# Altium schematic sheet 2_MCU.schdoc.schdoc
size 309 x 223 mm; Symbol: Artery_A4; Device: Artery_A4; Company: Artery Technology; Version: 1.1; Page Size: A4; @Project Name: AT-START-F423 V1.1; @Page Count: 4; @Update Date: 2024-04-30; @Create Date: 2023-04-24; @Schematic Name: AT-START-F423 V1.1; @Page No: 2; @Page Name: MCU
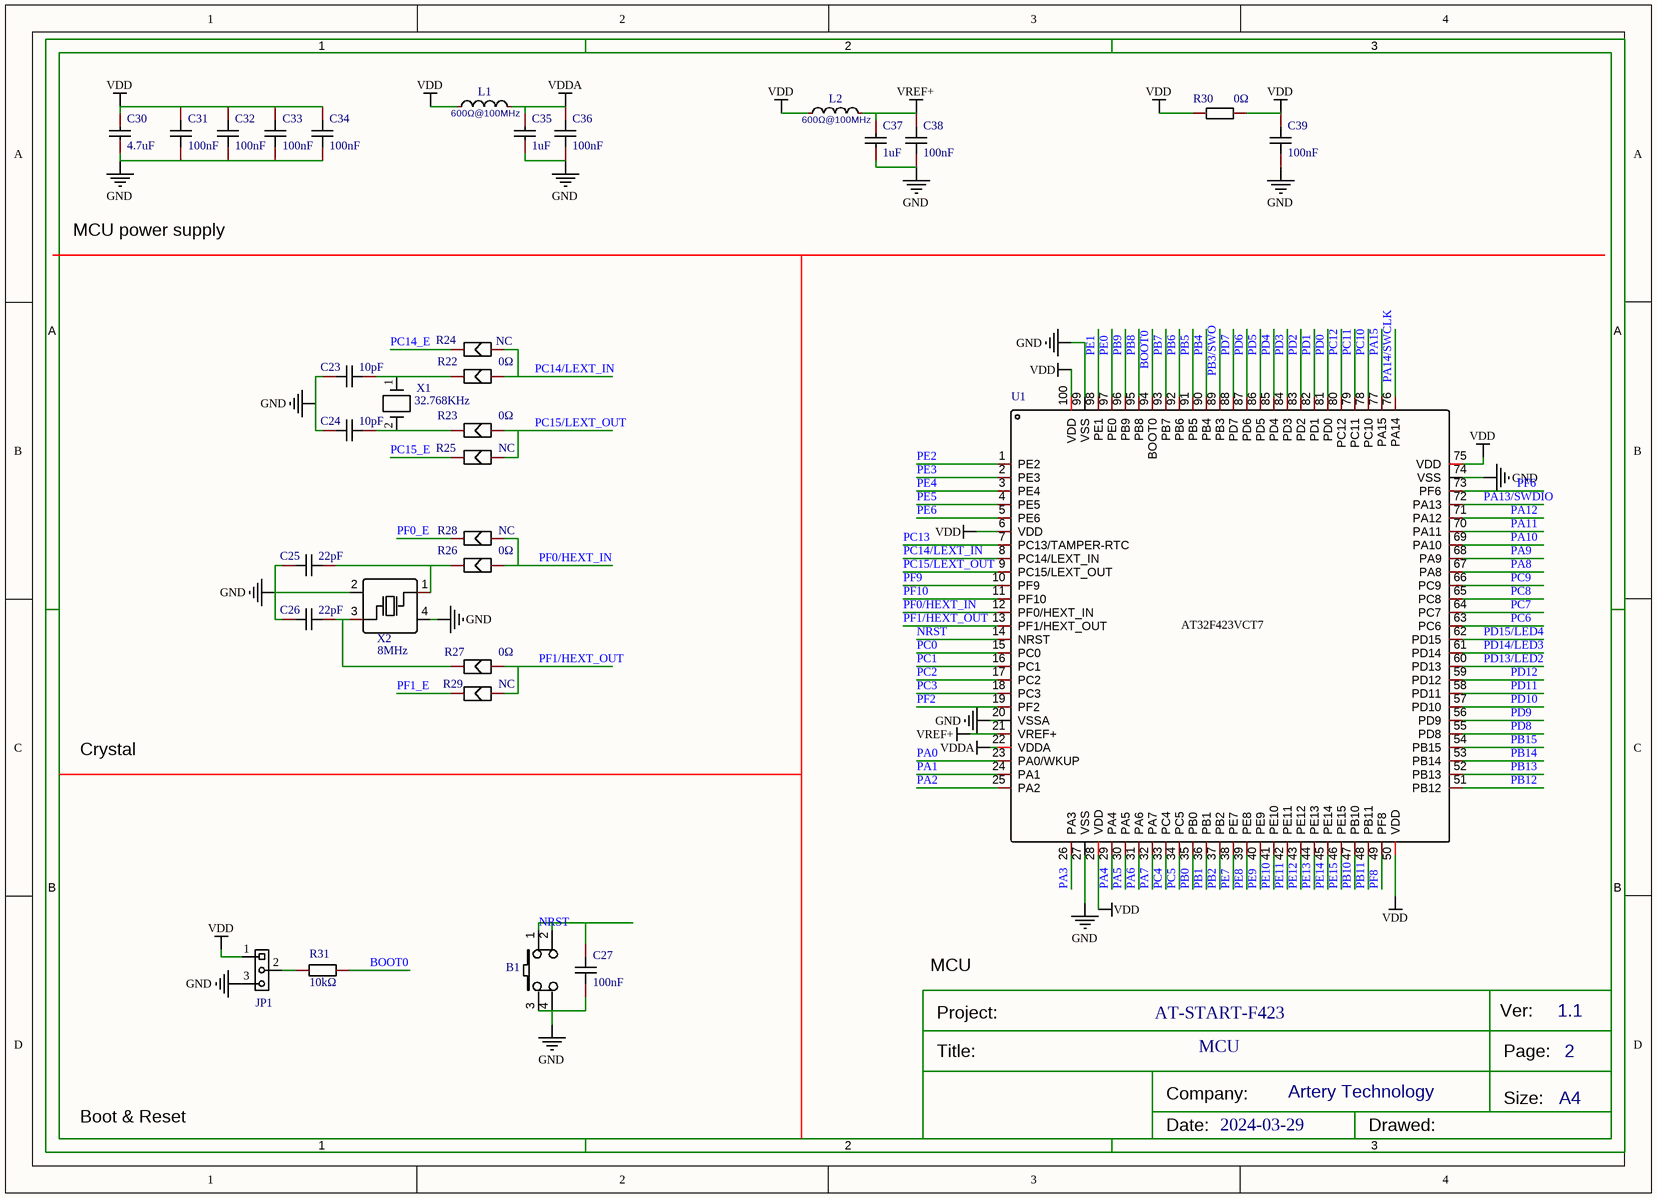
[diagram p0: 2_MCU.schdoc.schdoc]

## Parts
B1  BUTTON_SMT,6.0x6.0x4.5mm  [BUTTON_SMT_6*6*5]  (value not drawn)
C23  10pF  [0603_C-M]
C24  10pF  [0603_C-M]
C25  22pF  [0603_C-M(1)]
C26  22pF  [0603_C-M(1)]
C27  value 100nF  [C0603]  (hidden comment: CC0603KRX7R9BB104)
C30  value 4.7uF  [C0603]  (hidden comment: CL10A475KO8NNNC)
C31  value 100nF  [C0603]  (hidden comment: CC0603KRX7R9BB104)
C32  value 100nF  [C0603]  (hidden comment: CC0603KRX7R9BB104)
C33  value 100nF  [C0603]  (hidden comment: CC0603KRX7R9BB104)
C34  value 100nF  [C0603]  (hidden comment: CC0603KRX7R9BB104)
C35  value 1uF  [C0603]  (hidden comment: CL10A105KB8NNNC)
C36  value 100nF  [C0603]  (hidden comment: CC0603KRX7R9BB104)
C37  value 1uF  [C0603]  (hidden comment: CL10A105KB8NNNC)
C38  value 100nF  [C0603]  (hidden comment: CC0603KRX7R9BB104)
C39  value 100nF  [C0603]  (hidden comment: CC0603KRX7R9BB104)
JP1  Header 1x3  [HEADER 1X3]  (value not drawn)
L1  Impedance @ Frequency: 600Ω@100MHz  [L0603]  (hidden comment: UPZ1608E601-1R0TF)
L2  Impedance @ Frequency: 600Ω@100MHz  [L0603]  (hidden comment: UPZ1608E601-1R0TF)
R22  0Ω  [SB-PAD]
R23  0Ω  [SB-PAD]
R24  NC  [SB-PAD]
R25  NC  [SB-PAD]
R26  0Ω  [SB-PAD]
R27  0Ω  [SB-PAD]
R28  NC  [SB-PAD]
R29  NC  [SB-PAD]
R30  value 0Ω  [R0603]  (hidden comment: 0603WAF0000T5E)
R31  value 10kΩ  [R0603]  (hidden comment: 0603WAF1002T5E)
U1  AT32F423VCT7  [LQFP-100_L14.0-W14.0-P0.50-LS16.0-TL]  (value not drawn)
X1  32.768KHz  [XTAL_SOP - FC-12M]
X2  8MHz  [OSC-SMD_4P-L5.0-W3.2-BL]

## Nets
GND: B1.3 B1.4 C23.1 C24.1 C25.1 C26.1 C27.1 C30.1 C31.1 C32.1 C33.1 C34.1 C35.1 C36.1 C37.1 C38.1 C39.1 JP1.3 U1.20(VSSA) U1.27(VSS) U1.74(VSS) U1.99(VSS) X2.2(GND) X2.4(GND)
VDD: C30.2 C31.2 C32.2 C33.2 C34.2 C39.2 JP1.1 L1.1 L2.1 R30.1 R30.2 U1.6(VDD) U1.28(VDD) U1.50(VDD) U1.75(VDD) U1.100(VDD)
VDDA: C35.2 C36.2 L1.2 U1.22(VDDA)
VREF+: C37.2 C38.2 L2.2 U1.21(VREF+)
BOOT0: R31.2 U1.94(BOOT0)
NRST: B1.1 B1.2 C27.2 U1.14(NRST)
PA0: U1.23(PA0/WKUP)
PA1: U1.24(PA1)
PA2: U1.25(PA2)
PA3: U1.26(PA3)
PA4: U1.29(PA4)
PA5: U1.30(PA5)
PA6: U1.31(PA6)
PA7: U1.32(PA7)
PA8: U1.67(PA8)
PA9: U1.68(PA9)
PA10: U1.69(PA10)
PA11: U1.70(PA11)
PA12: U1.71(PA12)
PA13/SWDIO: U1.72(PA13)
PA14/SWCLK: U1.76(PA14)
PA15: U1.77(PA15)
PB0: U1.35(PB0)
PB1: U1.36(PB1)
PB2: U1.37(PB2)
PB3/SWO: U1.89(PB3)
PB4: U1.90(PB4)
PB5: U1.91(PB5)
PB6: U1.92(PB6)
PB7: U1.93(PB7)
PB8: U1.95(PB8)
PB9: U1.96(PB9)
PB10: U1.47(PB10)
PB11: U1.48(PB11)
PB12: U1.51(PB12)
PB13: U1.52(PB13)
PB14: U1.53(PB14)
PB15: U1.54(PB15)
PC0: U1.15(PC0)
PC1: U1.16(PC1)
PC2: U1.17(PC2)
PC3: U1.18(PC3)
PC4: U1.33(PC4)
PC5: U1.34(PC5)
PC6: U1.63(PC6)
PC7: U1.64(PC7)
PC8: U1.65(PC8)
PC9: U1.66(PC9)
PC10: U1.78(PC10)
PC11: U1.79(PC11)
PC12: U1.80(PC12)
PC13: U1.7(PC13/TAMPER-RTC)
PC14/LEXT_IN: R22.1 R24.1 U1.8(PC14/LEXT_IN)
PC14_E: R24.2
PC15/LEXT_OUT: R23.1 R25.1 U1.9(PC15/LEXT_OUT)
PC15_E: R25.2
PD0: U1.81(PD0)
PD1: U1.82(PD1)
PD2: U1.83(PD2)
PD3: U1.84(PD3)
PD4: U1.85(PD4)
PD5: U1.86(PD5)
PD6: U1.87(PD6)
PD7: U1.88(PD7)
PD8: U1.55(PD8)
PD9: U1.56(PD9)
PD10: U1.57(PD10)
PD11: U1.58(PD11)
PD12: U1.59(PD12)
PD13/LED2: U1.60(PD13)
PD14/LED3: U1.61(PD14)
PD15/LED4: U1.62(PD15)
PE0: U1.97(PE0)
PE1: U1.98(PE1)
PE2: U1.1(PE2)
PE3: U1.2(PE3)
PE4: U1.3(PE4)
PE5: U1.4(PE5)
PE6: U1.5(PE6)
PE7: U1.38(PE7)
PE8: U1.39(PE8)
PE9: U1.40(PE9)
PE10: U1.41(PE10)
PE11: U1.42(PE11)
PE12: U1.43(PE12)
PE13: U1.44(PE13)
PE14: U1.45(PE14)
PE15: U1.46(PE15)
PF0/HEXT_IN: R26.1 R28.1 U1.12(PF0/HEXT_IN)
PF0_E: R28.2
PF1/HEXT_OUT: R27.1 R29.1 U1.13(PF1/HEXT_OUT)
PF1_E: R29.2
PF2: U1.19(PF2)
PF6: U1.73(PF6)
PF8: U1.49(PF8)
PF9: U1.10(PF9)
PF10: U1.11(PF10)
NetC23_2: C23.2 R22.2 X1.1
NetC24_2: C24.2 R23.2 X1.2
NetC25_2: C25.2 R26.2 X2.1(OSC1)
NetC26_2: C26.2 R27.2 X2.3(OSC2)
NetJP1_2: JP1.2 R31.1

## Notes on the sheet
- MCU power supply
- Crystal
- MCU
- AT-START-F423
- Boot & Reset
- 2024-03-29

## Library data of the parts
B1 = BUTTON_SMT,6.0x6.0x4.5mm: Convert to PCB: yes
C23 = 10pF: Convert to PCB: yes
C24 = 10pF_0603_C-M: Convert to PCB: yes
C25 C26 = 22pF_0603_C-M: Convert to PCB: yes
C27 C31-C34 C36 C38 C39 = CC0603KRX7R9BB104: Manufacturer: YAGEO(国巨); Add into BOM: yes; Tolerance: ±10%; Voltage Rated: 50V; Temperature Coefficient: X7R; Description: 容值:100nF;精度:±10%;额定电压:50V;温度系数:X7R;
C30 = CL10A475KO8NNNC: Manufacturer: SAMSUNG(三星); Add into BOM: yes; Tolerance: ±10%; Voltage Rated: 16V; Temperature Coefficient: X5R; Description: 容值:4.7uF;精度:±10%;额定电压:16V;温度系数:X5R;
C35 C37 = CL10A105KB8NNNC: Manufacturer: SAMSUNG(三星); Add into BOM: yes; Tolerance: ±10%; Voltage Rated: 50V; Temperature Coefficient: X5R; Description: 容值:1uF;精度:±10%;额定电压:50V;温度系数:X5R;
JP1 = Header 1x3: Convert to PCB: yes
L1 L2 = UPZ1608E601-1R0TF: Manufacturer: Sunlord(顺络); Add into BOM: yes; Tolerance: ±25%; DC Resistance: 150mΩ; Current Rating: 1A; Circuits: 1; Description: 标称阻抗@测试频率:600Ω@100MHz;误差:±25%;直流电阻(RDC):150mΩ;额定电流:1A;电路数:1;
R22 R23 R26 R27 = NC_SB-PAD: Symbol: NC; Convert to PCB: yes
R24 R28 R29 = NC_SB-PAD: Convert to PCB: yes
R25 = NC: Convert to PCB: yes
R30 = 0603WAF0000T5E: 电阻类型:厚膜电阻;阻值:0Ω;精度:±1%;功率:1/10W;温度系数:-;最大工作电压:75V;工作温度范围:-55~+155;; Manufacturer: UNI-ROYAL(厚声); Add into BOM: yes; Tolerance: ±1%; Power(Watts): 1/10W; Overload Voltage (Max): 75V
R31 = 0603WAF1002T5E: 电阻类型:厚膜电阻;阻值:10kΩ;精度:±1%;功率:1/10W;温度系数:±100ppm/;最大工作电压:75V;工作温度范围:-55~+155;; Manufacturer: UNI-ROYAL(厚声); Add into BOM: yes; Tolerance: ±1%; Power(Watts): 1/10W; Overload Voltage (Max): 75V
U1 = AT32F423VCT7: Symbol: AT32F423VxT7
X1 = 32.768KHz: Convert to PCB: yes
X2 = 8MHz_OSC-SMD_4P-L5.0-W3.2-BL: Manufacturer: YXC; Manufacturer Part: X50328MSD4SC; Paste Type: recommend; Convert to PCB: yes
